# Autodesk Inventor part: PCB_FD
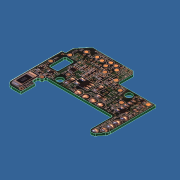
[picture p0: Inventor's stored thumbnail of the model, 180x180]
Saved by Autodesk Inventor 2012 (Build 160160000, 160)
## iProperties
Created: 2011-10
Part Number: PCB_FD
Document SubType Name: Modeling
Designer: Laur
Density: 1.38 g/cm^3
Material: Phénolique
Mass: 0.575758 g
Surface Area: 11.4869 cm^2
Volume: 0.417216 cm^3
Author: Laur
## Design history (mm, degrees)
sketch "Esquisse1"
  geometry: L1 (0.2, 0.766)-(0.2, 5.566); L2 (0.2, 5.566)-(-0.8, 6.566); L3 (-0.8, 6.566)-(-14.57, 6.566); L4 (-14.95, 6.392)-(-17.68, 3.207); L5 (-17.8, 2.881)-(-17.8, 0.766); L6 (-18.3, 0.266)-(-19, 0.266); L7 (-19, 0.266)-(-19, -16.934); L8 (-17, -18.934)-(-13.9, -18.934); L9 (-13.9, -18.934)-(-13.9, -14.034); L10 (-13.9, -14.034)-(-14.65, -14.034); L11 (-15.15, -13.534)-(-15.15, -12.234); L12 (-14.65, -11.734)-(-14.4, -11.734); L13 (-13.9, -11.234)-(-13.9, -10.934); L14 (-13.4, -10.434)-(8.7, -10.434); L15 (9.2, -10.934)-(9.2, -17.684); L16 (13.3, -15.43)-(13.3, 0.266); L17 (13.3, 0.266)-(0.7, 0.266); L18 (13.6, -18.934)-(3.914, -18.934); L19 (11.424, -18.467)-(12.859, -16.683); L20 (-27.6, 12.519)-(22.168, 12.519); L21 (22.168, 12.519)-(22.168, -24.807); L22 (22.168, -24.807)-(-27.6, -24.807); L23 (-27.6, -24.807)-(-27.6, 12.519); L24 (0, -32.272)-(0, 19.984) reference; L25 (-37.554, 0)-(32.121, 0) reference; A1 r 2 centre (-17, -16.934) between (-19, -16.934) and (-17, -18.934); A2 r 1.25 centre (10.45, -17.684) between (9.2, -17.684) and (11.424, -18.467); A3 r 2 centre (11.3, -15.43) between (12.859, -16.683) and (13.3, -15.43); A4 r 0.5 centre (0.7, 0.766) between (0.2, 0.766) and (0.7, 0.266); A5 r 0.5 centre (-18.3, 0.766) between (-18.3, 0.266) and (-17.8, 0.766); A6 r 0.5 centre (-14.65, -12.234) between (-14.65, -11.734) and (-15.15, -12.234); A7 r 0.5 centre (-14.65, -13.534) between (-15.15, -13.534) and (-14.65, -14.034); A8 r 0.5 centre (-14.4, -11.234) between (-14.4, -11.734) and (-13.9, -11.234); A9 r 0.5 centre (-13.4, -10.934) between (-13.4, -10.434) and (-13.9, -10.934); A10 r 0.5 centre (8.7, -10.934) between (9.2, -10.934) and (8.7, -10.434); A11 r 0.5 centre (-17.3, 2.881) between (-17.68, 3.207) and (-17.8, 2.881); A12 r 0.5 centre (-14.57, 6.066) between (-14.57, 6.566) and (-14.95, 6.392); 11 further points; 1 other entity
  constraints: 38 end point, 25 tangent, 24 point on circle, 20 point on line, 14 parallel, 12 centre point, 7 equal radius, 2 collinear, 2 vertical, 1 perpendicular, 2 other
  dimensions: "d0" = 1 distance from line of L3 L1.end; "d1" = 1 horizontal distance of L2.end L1.end (= d0); "d2" = 6.3 distance between parallel lines of L17 L3; "d3" = 3 horizontal distance of point (-17.8, 3.066) point (-14.8, 6.566); "d4" = 3.5 vertical distance of point (-17.8, 3.066) point (-14.8, 6.566); "d6" = 1.2 distance between parallel lines of L7 L5; "d7" = 2.8 distance from line of point (-17.8, 3.066) L6; "d8" = 19.2 distance between parallel lines of L8 L6; "d9" = 4.9 distance between parallel lines of L8 L10; "d10" = 5.1 distance between parallel lines of L7 L9; "d11" = 3.85 distance between parallel lines of L11 L7; "d12" = 2.3 distance between parallel lines of L10 L12; "d13" = 8.5 distance between parallel lines of L14 L8; "d14" = 23.1 distance between parallel lines of L15 L13; "d15" = 4.1 distance between parallel lines of L16 L15; "d17" = 32.3 distance between parallel lines of L16 L7 (derived); "d253" = 2 radius of A1; "d254" = 2.5 diameter of A2; "d256" = 2.8 distance from line of point (13.3, -16.134) L18; "d257" = 2 radius of A3; "d258" = 0.5 radius of A4; "d259" = 0.5 radius of A5; "d457" = 27.6 distance between parallel lines of L24 L23; "d460" = 12.51888 distance between parallel lines of L20 L25; "d461" = 13.1 distance between parallel lines of L1 L16; "d472" = 13.3 distance between parallel lines of L24 L16
  node "Image4"
extrude "contour" new body sketch "Esquisse1" distance "d18" = 0.8; taper "d19" = 0 deg
feature "recto PCB"
sketch "Esquisse3"
  geometry: L1 (-16.239, -0.883)-(-14.189, -0.883); L2 (-13.689, -1.383)-(-13.689, -6.033); L3 (-14.189, -6.533)-(-16.239, -6.533); L4 (-16.739, -6.033)-(-16.739, -1.383); C1 r 1.075 at (-10.769, -8.617); C2 r 1.075 at (5.731, -1.417); A1 r 0.5 centre (-16.239, -1.383) between (-16.239, -0.883) and (-16.739, -1.383); A2 r 0.5 centre (-14.189, -1.383) between (-13.689, -1.383) and (-14.189, -0.883); A3 r 0.5 centre (-16.239, -6.033) between (-16.739, -6.033) and (-16.239, -6.533); A4 r 0.5 centre (-14.189, -6.033) between (-14.189, -6.533) and (-13.689, -6.033)
  constraints: 8 end point, 8 point on circle, 8 tangent, 6 centre point, 3 equal radius, 2 parallel, 1 horizontal, 1 perpendicular
  dimensions: "d473" = 0.5 radius of A1; "d474" = 5.65 distance between parallel lines of L3 L1; "d475" = 3.05 distance between parallel lines of L2 L4; "d476" = 2.15 diameter of C1; "d477" = 2.15 diameter of C2; "d581" = 18.0025 distance of C2.centre C1.centre; "d582" = 7.2 vertical distance of C2.centre C1.centre
extrude "passages" cut sketch "Esquisse3" stored distance "d478" = 0.8; taper "d479" = 0 deg
sketch "Esquisse4"
  geometry: L1 (-0.7, 0.266)-(-13.3, 0.266) reference; L2 (-13.3, 0.266)-(-13.3, -15.43) reference; L3 (19, -16.934)-(19, 0.266) reference; L4 (23.726, -21.606)-(-17.909, -22.26); L5 (-17.909, -22.26)-(-18.4, 8.966); L6 (-18.4, 8.966)-(23.235, 9.62); L7 (23.235, 9.62)-(23.726, -21.606); 1 other entity
  constraints: 2 other
  dimensions: "d575" = 0.9 deg angle of L7 L3; "d577" = 8.7 distance from line of L5.end L1; "d578" = 5.1 distance from line of L5.end L2
feature "verso PCB" sketch "Esquisse4"
node "Solide1"
node "Corps solides"
node "Corps surfaciques"
node "Image6"
